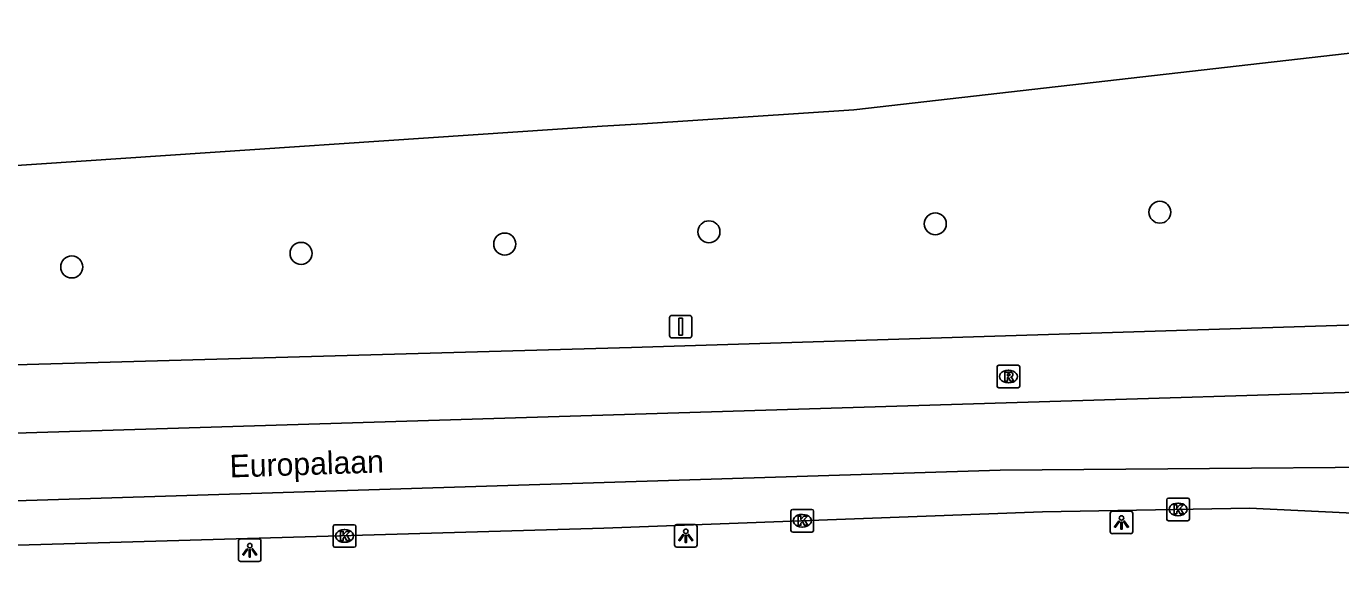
# Model space of a CAD drawing. Extents: x 161253 to 161848, y 384872 to 385383.
# Drawn here: x 161722.7 to 161781, y 385356.8 to 385380.9 of the extents above; entities that cross this region are included whole.
import ezdxf

# ---------------------------------------------------------------- set-up
doc = ezdxf.new("R2010")
doc.units = 0
for name, color, linetype in [('IMGEO_Boom', 7, 'Continuous'), ('IMGEO_Kolk', 7, 'Continuous'), ('IMGEO_Lichtpunt', 7, 'Continuous'), ('IMGEO_Openbare_ruimte_label', 7, 'Continuous'), ('IMGEO_Rijbaan_lokaal_gesloten', 7, 'Continuous'), ('IMGEO_Rioolput', 7, 'Continuous'), ('IMGEO_Verkeersbordpaal', 7, 'Continuous')]:
    doc.layers.add(name, color=color, linetype=linetype)

msp = doc.modelspace()

# ---------------------------------------------------------------- linework, layer by layer
at = {"layer": 'IMGEO_Boom'}
for centre in [(161772.959, 385372.616), (161752.957, 385371.745), (161762.999, 385372.099), (161743.902, 385371.201), (161734.87, 385370.786), (161724.698, 385370.185)]:
    msp.add_circle(centre, 0.489, dxfattribs=at)
at = {"layer": 'IMGEO_Kolk'}
for p, q in [((161773.343, 385359.922), (161774.195, 385359.922)), ((161756.598, 385358.493), (161756.598, 385359.345)), ((161756.673, 385359.419), (161757.525, 385359.419)), ((161757.599, 385359.345), (161757.599, 385358.493)), ((161773.268, 385358.996), (161773.268, 385359.848)), ((161773.756, 385359.702), (161773.781, 385359.702)), ((161774.269, 385359.848), (161774.269, 385358.996)), ((161736.371, 385358.745), (161737.223, 385358.745)), ((161757.086, 385359.199), (161757.111, 385359.199)), ((161774.195, 385358.922), (161773.343, 385358.922)), ((161773.779, 385359.142), (161773.754, 385359.142)), ((161736.296, 385357.819), (161736.296, 385358.671)), ((161736.784, 385358.525), (161736.809, 385358.525)), ((161737.297, 385358.671), (161737.297, 385357.819)), ((161757.525, 385358.419), (161756.673, 385358.419)), ((161757.109, 385358.639), (161757.084, 385358.639)), ((161737.223, 385357.745), (161736.371, 385357.745)), ((161736.807, 385357.965), (161736.782, 385357.965))]:
    msp.add_line(p, q, dxfattribs=at)
for points in [[(161773.343, 385359.922), (161774.195, 385359.922)], [(161756.598, 385358.493), (161756.598, 385359.345)], [(161756.673, 385359.419), (161757.525, 385359.419)], [(161757.599, 385359.345), (161757.599, 385358.493)], [(161773.268, 385358.996), (161773.268, 385359.848)], [(161773.589, 385359.622), (161773.712, 385359.622), (161773.712, 385359.471), (161773.842, 385359.622), (161774.006, 385359.622), (161773.86, 385359.471), (161774.013, 385359.222), (161773.861, 385359.222), (161773.776, 385359.386), (161773.712, 385359.319), (161773.712, 385359.222), (161773.589, 385359.222), (161773.589, 385359.622)], [(161774.269, 385359.848), (161774.269, 385358.996)], [(161736.371, 385358.745), (161737.223, 385358.745)], [(161756.919, 385359.119), (161757.042, 385359.119), (161757.042, 385358.968), (161757.172, 385359.119), (161757.336, 385359.119), (161757.19, 385358.968), (161757.343, 385358.719), (161757.191, 385358.719), (161757.106, 385358.883), (161757.042, 385358.816), (161757.042, 385358.719), (161756.919, 385358.719), (161756.919, 385359.119)], [(161774.195, 385358.922), (161773.343, 385358.922)], [(161736.296, 385357.819), (161736.296, 385358.671)], [(161736.617, 385358.445), (161736.74, 385358.445), (161736.74, 385358.294), (161736.87, 385358.445), (161737.034, 385358.445), (161736.888, 385358.294), (161737.041, 385358.045), (161736.889, 385358.045), (161736.804, 385358.209), (161736.74, 385358.142), (161736.74, 385358.045), (161736.617, 385358.045), (161736.617, 385358.445)], [(161737.297, 385358.671), (161737.297, 385357.819)], [(161757.525, 385358.419), (161756.673, 385358.419)], [(161737.223, 385357.745), (161736.371, 385357.745)]]:
    msp.add_lwpolyline(points, dxfattribs=at)
for centre, start, end in [((161773.345, 385359.846), 91.55205, 178.44795), ((161773.345, 385359.846), 91.55205, 178.44795), ((161774.193, 385359.846), 1.55205, 88.44795), ((161774.193, 385359.846), 1.55205, 88.44795), ((161756.675, 385359.343), 91.55205, 178.44795), ((161756.675, 385359.343), 91.55205, 178.44795), ((161757.523, 385359.343), 1.55205, 88.44795), ((161757.523, 385359.343), 1.55205, 88.44795), ((161736.373, 385358.669), 91.55205, 178.44795), ((161736.373, 385358.669), 91.55205, 178.44795), ((161737.221, 385358.669), 1.55205, 88.44795), ((161737.221, 385358.669), 1.55205, 88.44795), ((161773.345, 385358.998), 181.55205, 268.44795), ((161773.345, 385358.998), 181.55205, 268.44795), ((161774.193, 385358.998), 271.55205, 358.44795), ((161774.193, 385358.998), 271.55205, 358.44795), ((161756.675, 385358.495), 181.55205, 268.44795), ((161756.675, 385358.495), 181.55205, 268.44795), ((161757.523, 385358.495), 271.55205, 358.44795), ((161757.523, 385358.495), 271.55205, 358.44795), ((161736.373, 385357.821), 181.55205, 268.44795), ((161736.373, 385357.821), 181.55205, 268.44795), ((161737.221, 385357.821), 271.55205, 358.44795), ((161737.221, 385357.821), 271.55205, 358.44795)]:
    msp.add_arc(centre, 0.0765, start, end, dxfattribs=at)
for centre, major_axis, ratio, start_param, end_param in [((161773.755, 385359.422), (-0.387, 0.002), 0.722429, 4.712389, 7.853982), ((161773.78, 385359.422), (-0.39, 0.002), 0.717154, 1.570796, 4.712389), ((161757.085, 385358.919), (-0.387, 0.002), 0.722429, 4.712389, 7.853982), ((161757.11, 385358.919), (-0.39, 0.002), 0.717154, 1.570796, 4.712389), ((161736.783, 385358.245), (-0.387, 0.002), 0.722429, 4.712389, 7.853982), ((161736.808, 385358.245), (-0.39, 0.002), 0.717154, 1.570796, 4.712389)]:
    msp.add_ellipse(centre, major_axis=major_axis, ratio=ratio, start_param=start_param, end_param=end_param, dxfattribs=at)
at = {"layer": 'IMGEO_Lichtpunt'}
for p, q in [((161771.661, 385359.342), (161770.853, 385359.342)), ((161771.661, 385359.342), (161770.853, 385359.342)), ((161752.338, 385358.748), (161751.53, 385358.748)), ((161752.338, 385358.748), (161751.53, 385358.748)), ((161770.759, 385359.247), (161770.759, 385358.44)), ((161770.759, 385359.247), (161770.759, 385358.44)), ((161771.755, 385358.44), (161771.755, 385359.247)), ((161771.755, 385358.44), (161771.755, 385359.247)), ((161751.436, 385358.653), (161751.436, 385357.846)), ((161751.436, 385358.653), (161751.436, 385357.846)), ((161752.432, 385357.846), (161752.432, 385358.653)), ((161752.432, 385357.846), (161752.432, 385358.653)), ((161770.853, 385358.346), (161771.661, 385358.346)), ((161770.853, 385358.346), (161771.661, 385358.346)), ((161732.093, 385358.015), (161732.093, 385357.208)), ((161732.093, 385358.015), (161732.093, 385357.208)), ((161732.995, 385358.11), (161732.187, 385358.11)), ((161732.995, 385358.11), (161732.187, 385358.11)), ((161733.089, 385357.208), (161733.089, 385358.015)), ((161733.089, 385357.208), (161733.089, 385358.015)), ((161751.53, 385357.752), (161752.338, 385357.752)), ((161751.53, 385357.752), (161752.338, 385357.752)), ((161732.187, 385357.114), (161732.995, 385357.114)), ((161732.187, 385357.114), (161732.995, 385357.114))]:
    msp.add_line(p, q, dxfattribs=at)
for points in [[(161771.133, 385358.911), (161771.172, 385358.883), (161770.984, 385358.621), (161770.946, 385358.648), (161771.133, 385358.911)], [(161771.235, 385358.863), (161771.282, 385358.863), (161771.282, 385358.541), (161771.235, 385358.541), (161771.235, 385358.863)], [(161771.345, 385358.883), (161771.383, 385358.91), (161771.57, 385358.648), (161771.531, 385358.62), (161771.345, 385358.883)], [(161751.81, 385358.317), (161751.849, 385358.289), (161751.661, 385358.027), (161751.623, 385358.054), (161751.81, 385358.317)], [(161751.912, 385358.269), (161751.959, 385358.269), (161751.959, 385357.947), (161751.912, 385357.947), (161751.912, 385358.269)], [(161752.022, 385358.289), (161752.06, 385358.316), (161752.247, 385358.054), (161752.208, 385358.026), (161752.022, 385358.289)], [(161732.467, 385357.679), (161732.506, 385357.651), (161732.318, 385357.389), (161732.28, 385357.416), (161732.467, 385357.679)], [(161732.569, 385357.631), (161732.616, 385357.631), (161732.616, 385357.309), (161732.569, 385357.309), (161732.569, 385357.631)], [(161732.679, 385357.651), (161732.717, 385357.678), (161732.904, 385357.416), (161732.865, 385357.388), (161732.679, 385357.651)]]:
    msp.add_lwpolyline(points, dxfattribs=at)
for centre in [(161771.258, 385359.045), (161751.935, 385358.451), (161732.592, 385357.813)]:
    msp.add_circle(centre, 0.0994, dxfattribs=at)
for centre, start, end in [((161770.853, 385359.247), 90, 180), ((161770.853, 385359.247), 90, 180), ((161771.661, 385359.247), 0, 90), ((161771.661, 385359.247), 0, 90), ((161751.53, 385358.653), 90, 180), ((161751.53, 385358.653), 90, 180), ((161752.338, 385358.653), 0, 90), ((161752.338, 385358.653), 0, 90), ((161770.853, 385358.44), 180, 270), ((161770.853, 385358.44), 180, 270), ((161771.661, 385358.44), 270, 0), ((161771.661, 385358.44), 270, 360), ((161732.187, 385358.015), 90, 180), ((161732.187, 385358.015), 90, 180), ((161732.995, 385358.015), 0, 90), ((161732.995, 385358.015), 0, 90), ((161751.53, 385357.846), 180, 270), ((161751.53, 385357.846), 180, 270), ((161752.338, 385357.846), 270, 0), ((161752.338, 385357.846), 270, 360), ((161732.187, 385357.208), 180, 270), ((161732.187, 385357.208), 180, 270), ((161732.995, 385357.208), 270, 0), ((161732.995, 385357.208), 270, 360)]:
    msp.add_arc(centre, 0.0946, start, end, dxfattribs=at)
at = {"layer": 'IMGEO_Rijbaan_lokaal_gesloten'}
for points in [[(161661.919, 385370.448), (161698.032, 385373.062), (161748.217, 385376.43), (161750.012, 385376.539), (161759.392, 385377.16), (161791.881, 385380.869)], [(161792.671, 385367.953), (161749.527, 385366.616), (161677.491, 385364.59), (161662.255, 385361.554)], [(161792.812, 385364.967), (161756.931, 385363.87), (161711.552, 385362.483), (161685.959, 385361.7), (161662.255, 385361.554)], [(161791.883, 385361.372), (161765.882, 385361.168), (161693.707, 385358.916), (161677.668, 385358.493), (161661.517, 385358.276), (161631.397, 385356.891)], [(161657.397, 385355.953), (161657.562, 385355.96), (161748.303, 385358.596), (161767.756, 385359.312), (161776.93, 385359.481), (161791.948, 385358.758)]]:
    msp.add_lwpolyline(points, dxfattribs=at)
at = {"layer": 'IMGEO_Rioolput'}
for p, q in [((161765.742, 385364.895), (161765.742, 385365.747)), ((161765.817, 385365.821), (161766.669, 385365.821)), ((161766.743, 385365.747), (161766.743, 385364.895)), ((161766.23, 385365.601), (161766.255, 385365.601)), ((161766.669, 385364.821), (161765.817, 385364.821)), ((161766.253, 385365.041), (161766.228, 385365.041))]:
    msp.add_line(p, q, dxfattribs=at)
for points in [[(161765.742, 385364.895), (161765.742, 385365.747)], [(161765.817, 385365.821), (161766.669, 385365.821)], [(161766.743, 385365.747), (161766.743, 385364.895)], [(161766.331, 385365.519), (161766.079, 385365.521), (161766.079, 385365.121)], [(161766.079, 385365.121), (161766.203, 385365.121), (161766.203, 385365.283), (161766.214, 385365.283)], [(161766.257, 385365.44), (161766.203, 385365.44), (161766.203, 385365.359)], [(161766.203, 385365.359), (161766.255, 385365.359)], [(161766.261, 385365.254), (161766.332, 385365.121), (161766.472, 385365.121), (161766.407, 385365.247)], [(161766.669, 385364.821), (161765.817, 385364.821)]]:
    msp.add_lwpolyline(points, dxfattribs=at)
for centre, radius, start, end in [((161765.819, 385365.745), 0.0765, 91.55205, 178.44795), ((161765.819, 385365.745), 0.0765, 91.55205, 178.44795), ((161766.667, 385365.745), 0.0765, 1.55205, 88.44795), ((161766.667, 385365.745), 0.0765, 1.55205, 88.44795), ((161766.213, 385365.23), 0.0533, 26.02933, 88.69889), ((161766.239, 385365.548), 0.19, 274.7715, 282.96867), ((161766.263, 385365.344), 0.0964, 77.00612, 93.18647), ((161766.277, 385365.401), 0.0378, 276.66336, 79.67722), ((161766.33, 385365.409), 0.109, 350.36119, 89.41601), ((161766.328, 385365.409), 0.112, 277.58423, 350.98172), ((161766.312, 385365.194), 0.108, 29.51342, 73.79051), ((161765.819, 385364.897), 0.0765, 181.55205, 268.44795), ((161765.819, 385364.897), 0.0765, 181.55205, 268.44795), ((161766.667, 385364.897), 0.0765, 271.55205, 358.44795), ((161766.667, 385364.897), 0.0765, 271.55205, 358.44795)]:
    msp.add_arc(centre, radius, start, end, dxfattribs=at)
for centre, major_axis, ratio, start_param, end_param in [((161766.229, 385365.321), (-0.387, 0.002), 0.722429, 4.712389, 7.853982), ((161766.254, 385365.321), (-0.39, 0.002), 0.717154, 1.570796, 4.712389)]:
    msp.add_ellipse(centre, major_axis=major_axis, ratio=ratio, start_param=start_param, end_param=end_param, dxfattribs=at)
at = {"layer": 'IMGEO_Verkeersbordpaal'}
for p, q in [((161751.21, 385367.136), (161751.21, 385367.936)), ((161751.21, 385367.936), (161751.21, 385367.136)), ((161751.31, 385368.036), (161752.1, 385368.036)), ((161752.1, 385368.036), (161751.31, 385368.036)), ((161752.2, 385367.936), (161752.2, 385367.136)), ((161752.2, 385367.136), (161752.2, 385367.936)), ((161752.1, 385367.036), (161751.31, 385367.036)), ((161751.31, 385367.036), (161752.1, 385367.036))]:
    msp.add_line(p, q, dxfattribs=at)
msp.add_lwpolyline([(161751.63, 385367.911), (161751.78, 385367.911), (161751.78, 385367.161), (161751.63, 385367.161), (161751.63, 385367.911)], dxfattribs=at)
for centre, start, end in [((161751.31, 385367.936), 90, 180), ((161751.31, 385367.936), 90, 180), ((161752.1, 385367.936), 0, 90), ((161752.1, 385367.936), 360, 90), ((161751.31, 385367.136), 180, 270), ((161751.31, 385367.136), 180, 270), ((161752.1, 385367.136), 270, 0), ((161752.1, 385367.136), 270, 0)]:
    msp.add_arc(centre, 0.1, start, end, dxfattribs=at)

# ---------------------------------------------------------------- texts
at = {"layer": 'IMGEO_Openbare_ruimte_label'}
msp.add_text('Europalaan', height=1, rotation=1.89197, dxfattribs=at).set_placement((161731.717, 385360.84))

doc.saveas('drawing.dxf')
